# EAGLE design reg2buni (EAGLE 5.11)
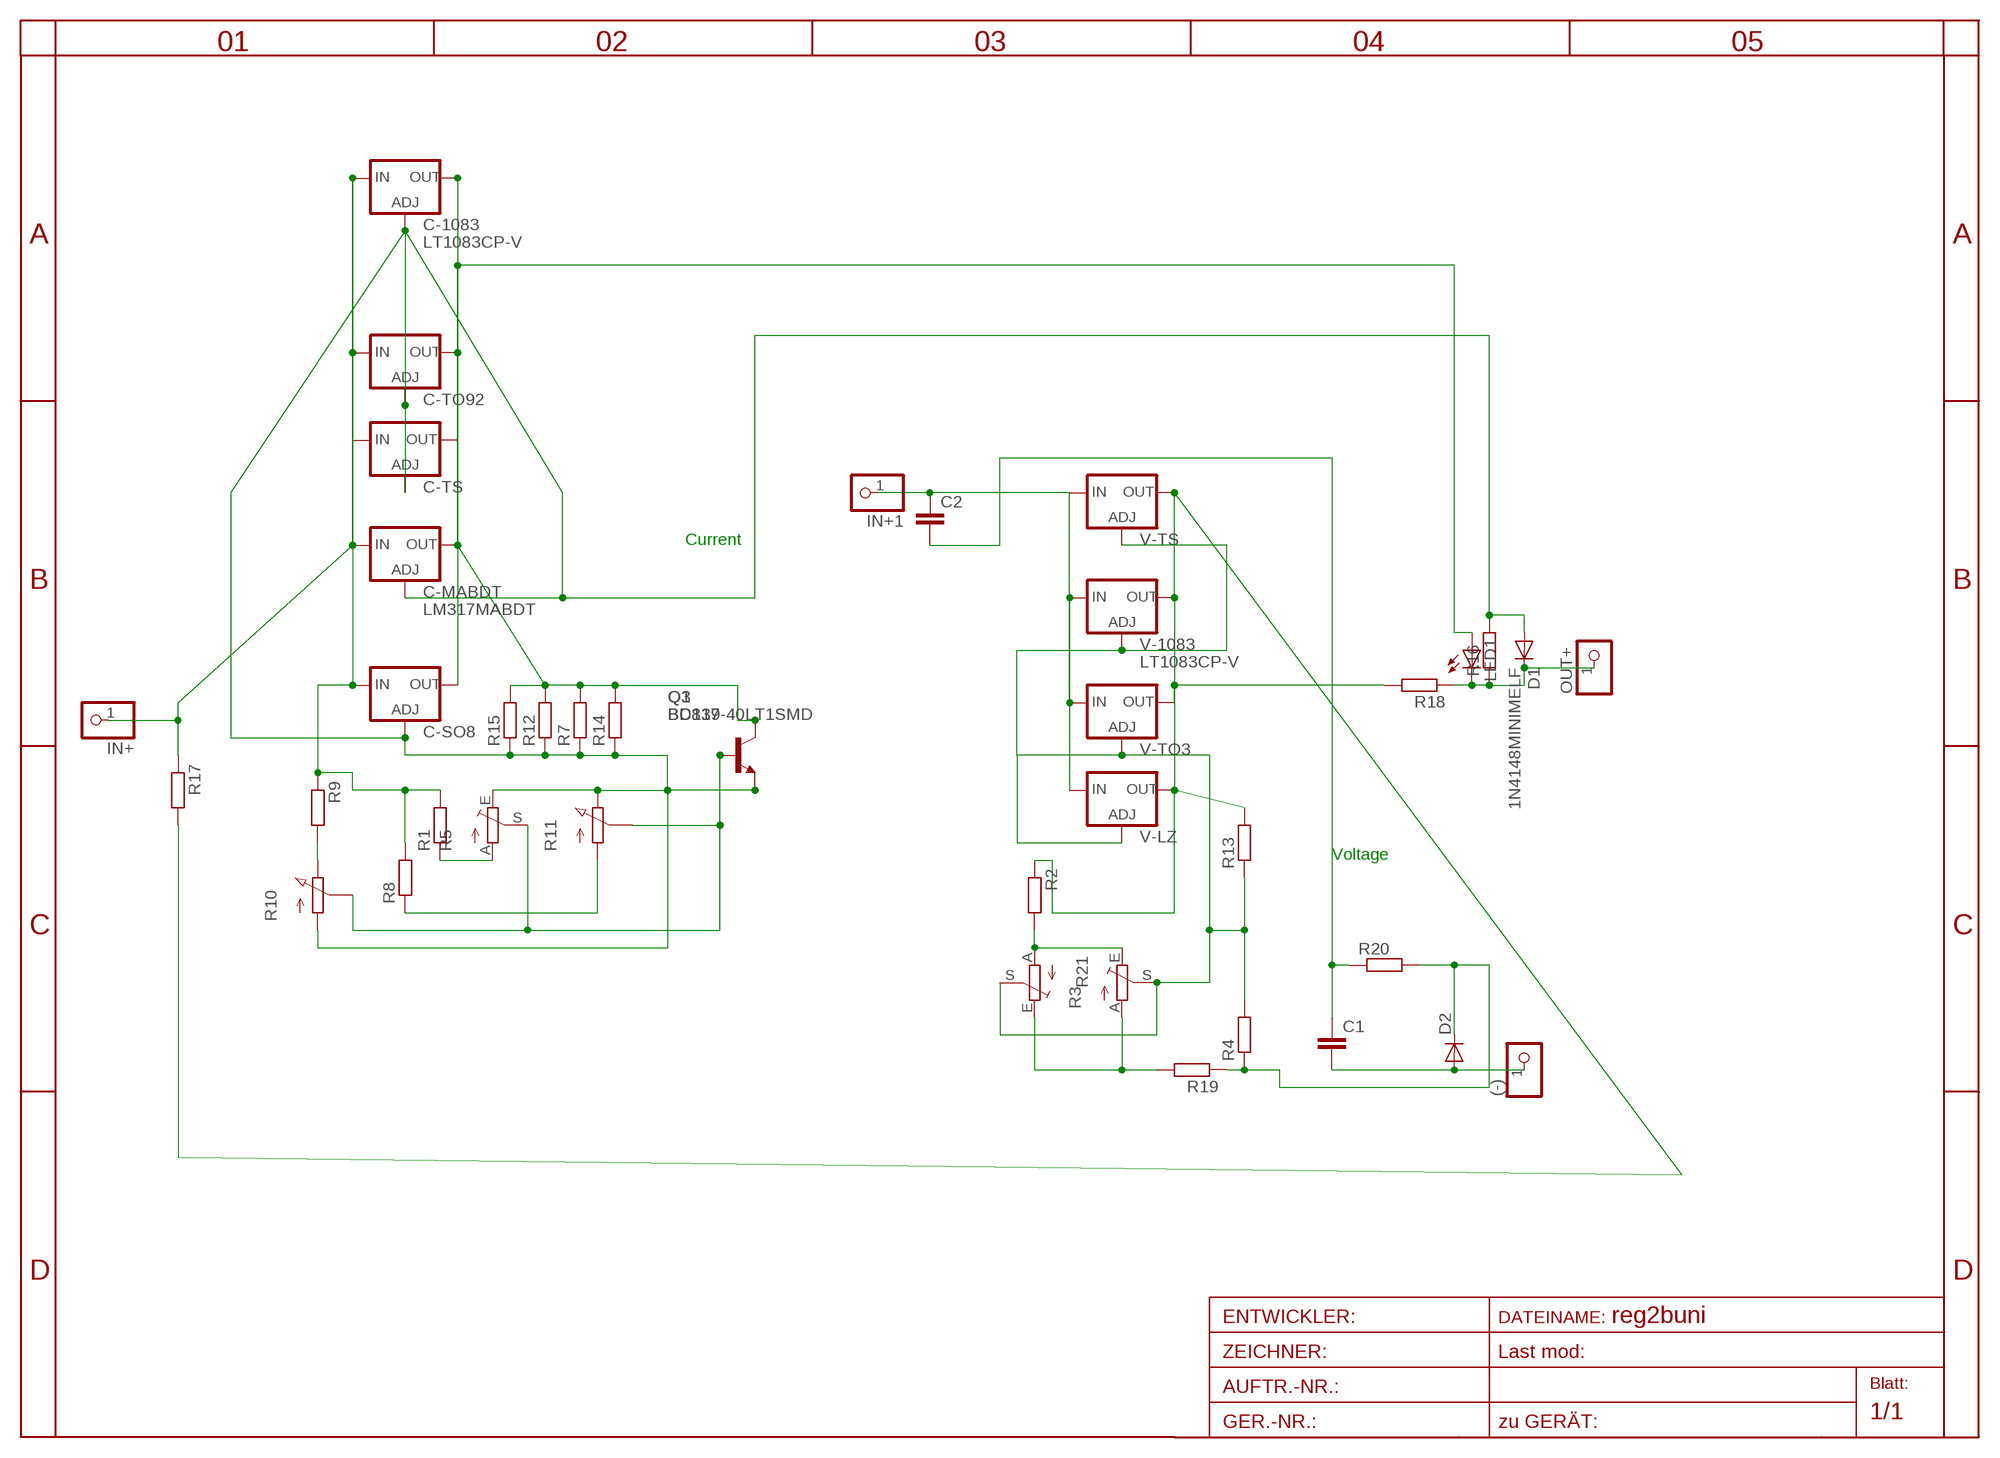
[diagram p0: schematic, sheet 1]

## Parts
(-)  PINHD-1X1  [1X01]
C1  C-EU050-025X075  [C050-025X075]
C2  C-EU050-025X075  [C050-025X075]
C-1083  LT1083CP-V  [TO247S]
C-MABDT  LM317MABDT  [DPACK]
C-SO8  LM317LM-OUTPIN7  [SO08]
C-TO92  LM317LZ  [317L]
C-TS  LM317TS  [317TS]
D1  1N4148MINIMELF  [MINIMELF]
D2  DIODE-MINIMELF  [MINIMELF]
IN+  PINHD-1X1  [1X01]
IN+1  PINHD-1X1  [1X01]
LED1  LEDCHIPLED_1206  [CHIPLED_1206]
OUT+  PINHD-1X1  [1X01]
Q1  BC817-40LT1SMD  [SOT23-BEC]
Q3  BD139  [TO126V]
R1  R-EU_0207/15  [0207/15]
R2  R-EU_0207/10  [0207/10]
R3  TRIM_EU-LI15  [LI15]
R4  R-EU_0204/7  [0204/7]
R5  TRIM_EU-LI15  [LI15]
R7  R-EU_R1206  [R1206]
R8  R-EU_R1206  [R1206]
R9  R-EU_R1206  [R1206]
R10  PC25  [PC25]
R11  PC25  [PC25]
R12  R-EU_R1206  [R1206]
R13  R-EU_0204/5  [0204/5]
R14  R-EU_R1206  [R1206]
R15  R-EU_R1206  [R1206]
R16  R-EU_R0402  [R0402]
R17  R-EU_R0402  [R0402]
R18  R-EU_R0402  [R0402]
R19  R-EU_R0402  [R0402]
R20  R-EU_0207/12  [0207/12]
R21  TRIM_EU-EVND_H  [EVND8AA]
V-1083  LT1083CP-V  [TO247S]
V-LZ  LM317LZ  [317L]
V-TO3  LM317-TO3  [TO3-K02]
V-TS  LM317TS  [317TS]

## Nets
ADJ2: R3.S R4.2 R13.1 R21.S V-1083.1(ADJ) V-LZ.1(ADJ) V-TO3.2(ADJ) V-TS.1(ADJ)
ADJUST: C-1083.1(ADJ) C-MABDT.1(ADJ) C-SO8.4(ADJ) C-TO92.1(ADJ) C-TS.1(ADJ) D1.A Q1.E Q3.3(E) R5.E R7.1 R10.A R11.E R12.1 R14.1 R15.1 R16.2
B1: Q1.B Q3.1(B) R5.S R10.S R11.S
IN+1: C2.1 IN+1.1 V-1083.3(IN) V-LZ.3(IN) V-TO3.1(IN) V-TS.3(IN)
IN-: (-).1 C1.2 D2.A
INPUT+: C-1083.3(IN) C-MABDT.3(IN) C-SO8.1(IN) C-TO92.3(IN) C-TS.3(IN) IN+.1 R1.2 R8.2 R9.1 R17.1
MINUS: R1.1 R5.A
N$1: R3.A R19.2 R21.E
N$2: R2.2 R3.E R21.A
N$5: R8.1 R11.A
N$6: R9.2 R10.E
N$7: C1.1 C2.2 R20.1
OUT1: C-1083.2(OUT) C-MABDT.4(OUT) C-SO8.7(OUT) C-TO92.2(OUT) C-TS.2(OUT) LED1.A Q1.C Q3.2(C) R7.2 R12.2 R14.2 R15.2
OUT2: R2.1 R13.2 R17.2 R18.2 V-1083.2(OUT) V-LZ.2(OUT) V-TO3.3(OUT) V-TS.2(OUT)
OUT+: D1.C LED1.C OUT+.1 R16.1 R18.1
VIRT-: D2.C R4.1 R19.1 R20.2

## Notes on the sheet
- Current
- Voltage

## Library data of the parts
(-) IN+ IN+1 OUT+ = pinhead(2):PINHD-1X1: PIN HEADER
C1 C2 = rcl:C-EU: CAPACITOR, European symbol
C-1083 V-1083 = linear-technology-2:LT1083*: 7.5A Low Dropout Positive Adjustable Regulators
C-MABDT = v-reg:LM317?*: 500 mA Adjustable Output Positive Voltage Regulator Source: http://www.onsemi.co.jp .. LM317M-D.PDF
C-SO8 C-TO92 V-LZ = v-reg-3:LM317L: Adjustable Voltage Regulator, 1.2V to 37V, 100mA
C-TS V-TS = v-reg:LM317TS: VOLTAGE REGULATOR
D1 = diode-1:1N4148: DIODE
D2 = diode:DIODE-: DIODE
LED1 = led:LED: LED
Q1 = transistor-npn:BC817*: NPN Transistor
Q3 = transistor-npn:BD139*: NPN Transistor
R1 R2 R4 R7-R9 R12-R20 = rcl-2:R-EU_: RESISTOR, European symbol
R3 R5 R21 = pot:TRIM_EU-: POTENTIOMETER
R10 R11 = pot-vitrohm:PC25: VITROHM POTENTIOMETER
V-TO3 = v-reg:LM317-TO3: VOLTAGE REGULATOR

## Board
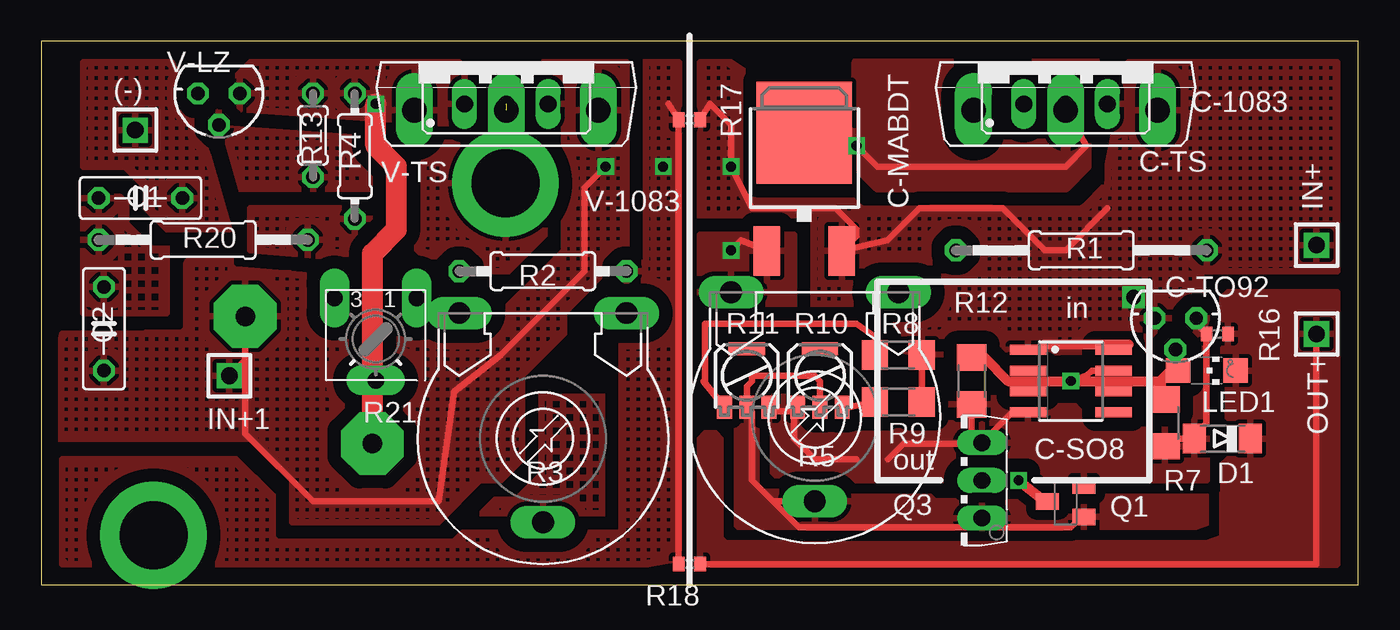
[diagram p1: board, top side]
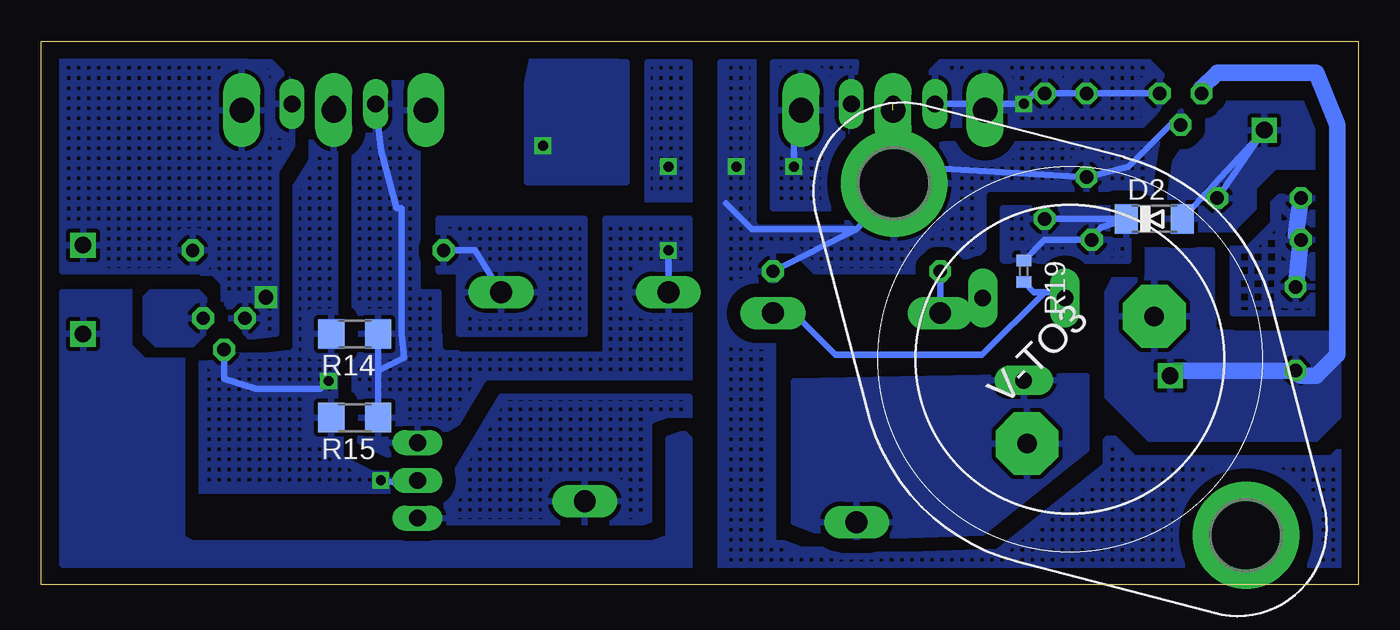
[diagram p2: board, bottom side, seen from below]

Size 80.01 x 33.02 mm. Coordinates in mm from the lower left corner, seen from the top.
Outline: 0,0 80.01,0 80.01,33.02 0,33.02 0,0
Copper layers (1*16): Top 0.035mm / dielectric 1.5mm / Bottom 0.035mm
Design rules "default": minimum track width 10mil, minimum drill 24mil, track to track 8mil, track to pad 8mil, pad to pad 8mil, via to via 8mil, smd to smd 8mil, copper to edge 40mil, drill to drill 8mil, minimum pad ring 10mil, minimum via ring 8mil, stop-mask expansion 4mil, vias tented up to drill 0mil, thermal gap 10mil

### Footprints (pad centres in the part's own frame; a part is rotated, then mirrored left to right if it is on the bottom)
1X01 = drill 1.016 square: 1 0,0
C050-025X075 = drill 0.813 octagon: 1 -2.54,0; 2 2.54,0
TO247S = drill 1.499 long: 1 -5.588,-2.921; 2 0,-2.921; 3 5.588,-2.921
DPACK = smd 1.6 x 3: 1 -2.28,-4.8; 3 2.28,-4.8 | smd 5.8 x 6.2: 4 0,2.38
SO08 = smd 0.6 x 2.2: 1 -1.905,-2.6; 2 -0.635,-2.6; 3 0.635,-2.6; 4 1.905,-2.6; 5 1.905,2.6; 6 0.635,2.6; 7 -0.635,2.6; 8 -1.905,2.6
317L = drill 0.813 octagon: 1 -1.27,0; 2 0,1.905; 3 1.27,0
317TS = drill 1.016 long: 1 -2.54,-2.54; 2 0,-2.54; 3 2.54,-2.54
MINIMELF = smd 1.4 x 1.8: A 1.7,0; C -1.7,0
CHIPLED_1206 = smd 1.5 x 1.5: A 0,-1.75; C 0,1.75
SOT23-BEC = smd 1 x 1.4: B -0.95,-1.1; C 0,1.1; E 0.95,-1.1
TO126V = drill 1.016 long: 1 -2.286,-1.27; 2 0,-1.27; 3 2.286,-1.27
0207/15 = drill 0.813 octagon: 1 -7.62,0; 2 7.62,0
0207/10 = drill 0.813 octagon: 1 -5.08,0; 2 5.08,0
LI15 = drill 1.321 long: A -5.08,-7.62; E 5.08,-7.62; S 0,5.08
0204/7 = drill 0.813 octagon: 1 -3.81,0; 2 3.81,0
R1206 = smd 1.6 x 1.803: 1 -1.422,0; 2 1.422,0
PC25 = smd 2.2 x 0.8: 4 0,1.65 | smd 0.9 x 1.4: A -1.35,-1.9; E 1.35,-1.9; S 0,-1.9
0204/5 = drill 0.813 octagon: 1 -2.54,0; 2 2.54,0
R0402 = smd 0.7 x 0.9: 1 -0.65,0; 2 0.65,0
0207/12 = drill 0.813 octagon: 1 -6.35,0; 2 6.35,0
EVND8AA = drill 1 pad 1.778 long: A -2.5,-2.5; E 2.5,-2.5; S 0,2.5
TO3-K02 = drill 1.194 pad 3.81 octagon: 1 -1.778,-5.461; 2 -1.778,5.461 | drill 4.115 pad 6.477 round: 3 15.113,0; 3@ -15.113,0

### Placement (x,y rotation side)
(-)  5.71,27.62 0 top
C1  6.03,23.5 0 top
C2  3.81,15.56 90 top
C-1083  62.23,31.75 0 top
C-MABDT  46.35,25.08 0 top
C-SO8  62.55,12.38 270 top
C-TO92  68.9,16.19 180 top
C-TS  62.23,31.75 0 top
D1  71.75,8.89 180 top
D2  12.38,22.23 0 bottom
IN+  77.47,20.64 0 top
IN+1  11.43,12.7 0 top
LED1  70.8,13.02 270 top
OUT+  77.47,15.24 0 top
Q1  62.23,5.08 90 top
Q3  55.88,6.35 90 top
R1  63.18,20.32 0 top
R2  30.48,19.05 180 top
R3  30.48,8.89 180 top
R4  19.05,26.04 90 top
R5  46.99,10.16 180 top
R7  68.26,9.84 90 top
R8  52.07,13.97 0 top
R9  52.07,11.11 180 top
R10  47.31,12.7 0 top
R11  42.86,12.7 0 top
R12  56.52,12.38 90 top
R13  16.51,27.3 270 top
R14  60.96,15.24 180 bottom
R15  60.96,10.16 180 bottom
R16  71.44,15.24 180 top
R17  39.37,28.26 180 top
R18  39.37,1.27 180 top
R19  20.32,19.05 270 bottom
R20  9.84,20.95 0 top
R21  20.32,14.92 180 top
V-1083  28.26,31.75 0 top
V-LZ  10.79,29.84 180 top
V-TO3  17.52,13.71 135 bottom
V-TS  28.26,31.75 0 top

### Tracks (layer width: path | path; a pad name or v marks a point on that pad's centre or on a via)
ADJ2  (via drill 0.6)
  Top 1.27: V-TO3.2 20.12,20.12 21.59,21.59 21.59,25.4 20.32,26.67 v20.32,29.21
  Bottom 0.406: V-LZ.1 R13.1 R4.2 19.68,29.84 v20.32,29.21 21.59,29.21 22.32,28.48 | 22.32,28.48 V-1083.1 23.05,29.21 V-TS.1 | 22.32,28.48 21.78,27.94
  pour Bottom (isolate 0.813, hatched): 11.43,30.48 12.7,31.75 25.4,31.75 26.67,30.48 26.67,29.21 25.4,27.94 12.7,27.94
  pour Bottom (isolate 0.813, rank 2): 16.51,12.7 34.29,12.38 34.29,3.81 31.75,2.86 22.86,3.17 16.51,8.26
  pour Top (isolate 0.813, rank 5, hatched): 29.21,11.43 34.29,11.43 34.29,3.81 25.4,3.81
  pour Top (isolate 0.813, hatched): 11.43,30.48 12.7,31.75 25.4,31.75 26.67,30.48 26.67,29.21 25.4,27.94 12.06,28.89
ADJUST  (via drill 0.6)
  Top 0.406: C-SO8.4 58.99,10.48 Q3.3 | 49.53,7.62 46.99,7.62 45.72,8.89 45.72,10.56 | 45.72,10.56 R10.A | 45.72,10.56 44.45,10.56 R11.E | 51.44,7.62 52.39,8.57 57.09,8.57 Q3.3 | R12.1 56.52,9.27 Q3.3 | C-MABDT.1 42.51,20.92 v41.91,20.32 | C-TO92.1 70.17,15.86 R16.2 70.79,9.83 69.85,8.89 68.43,8.89 R7.1
  Bottom 0.406: 59.69,10.01 R15.1 59.54,13.02 | C-TS.1 59.37,26.35 58.42,22.86 58.1,22.86 58.1,15.24 57.95,13.8 59.54,13.02 | 59.54,13.02 R14.1 | 57.4,8.89 57.15,8.89 | R5.E v41.91,20.32
  pour Bottom (isolate 0.813, rank 4, hatched): 45.72,22.23 40.64,22.23 40.64,10.16 52.07,11.43 58.42,7.62 60.96,8.89 60.96,30.48 57.15,30.48 57.15,17.78 55.88,17.78 55.88,15.24 54.61,13.97 45.72,13.97
  pour Top (isolate 0.813): 40.01,21.27 45.72,21.27 45.72,16.51 40.32,16.51 40.01,16.83
  pour Top (isolate 0.813): 44.45,11.43 44.45,6.35 70.8,6.35 70.8,16.83 67.31,11.43 66.04,10.16 63.5,10.16 62.23,11.43
  pour Bottom (isolate 0.61): 69.85,16.51 69.85,17.14 70.48,17.78 73.34,17.78 73.66,17.46 73.66,15.24 73.03,14.61 70.8,14.61 70.17,15.24
B1
  Top 0.406: R10.S 47.31,12.38 46.99,12.7 43.18,12.7 43.18,12.38 42.86,12.06 R11.S 43.18,10.48 43.18,6.35 44.45,5.08 | 44.45,5.08 R5.S | Q1.B 63.19,4.13 62.55,3.49 46.04,3.49 44.45,5.08
  pour Bottom (isolate 0.813, rank 3, hatched): 40.64,11.43 52.07,11.43 55.88,5.08 58.42,3.81 40.64,3.81
  pour Top (isolate 0.61, rank 3): 41.91,10.16 41.91,2.54 69.85,2.54 71.12,3.81 71.12,5.08 70.48,5.71 65.09,5.71 64.45,5.08 54.29,5.08 53.66,5.71 45.4,5.71 44.13,6.99 44.13,10.48
IN+1  (via drill 0.6)
  Top 0.406: v34.29,25.4 33.02,24.13 33.02,19.05 27.94,13.97 25.08,11.75 24.13,5.08 16.51,5.08 12.4,9.19 V-TO3.1 12.4,13.67 IN+1.1
  Bottom 0.406: 11.11,13.02 IN+1.1 | 3.49,12.7 C2.1 | v34.29,25.4 34.29,28.38 V-1083.3
  Bottom 1.016: C2.1 11.11,13.02 | V-LZ.3 9.53,30.16 8.57,31.11 2.54,31.11 1.27,27.94 1.27,13.97 2.54,12.7 3.49,12.7
  pour Bottom (isolate 0.813, hatched): 30.48,31.75 35.56,31.75 35.56,22.86 31.75,22.86
  pour Top (isolate 0.813, rank 3, hatched): 1.27,15.24 6.35,15.24 8.89,19.68 15.24,19.68 19.05,15.24 26.67,15.24 31.75,20.32 31.75,30.48 30.48,31.75 35.56,31.75 35.56,20.32 31.75,16.51 31.75,15.24 29.21,12.7 29.21,7.62 27.94,6.35 26.67,6.35 24.13,3.81 15.24,3.81 15.24,6.35 12.7,8.89 0,8.89
  pour Bottom (isolate 0.813, rank 3): 15.24,17.78 15.24,11.43 12.7,8.89 2.54,8.89 0,11.43 0,13.97 1.27,15.24 7.62,15.24 8.89,16.51 8.89,20.32 13.97,20.32
IN-
  Bottom 0.406: C1.2 (-).1 D2.A
  pour Bottom (isolate 0.813): 2.54,29.21 8.89,29.21 9.84,27.62 11.11,25.72 11.75,21.59 7.62,21.59 6.35,22.86 6.35,24.13 5.08,25.4 2.54,25.4
  pour Top (isolate 0.813, hatched): 2.54,31.75 7.94,31.75 10.16,26.04 11.43,21.59 7.62,21.59 6.35,22.86 6.35,24.13 5.08,25.4 2.54,25.4
INPUT+  (via drill 0.6, 0.9)
  Top 0.406: R9.1 R8.2 | C-SO8.1 60.64,14.29 60.96,14.61 | 64.77,22.86 62.23,20.32 60.96,20.32 58.42,22.86 53.34,22.86 51.4,20.92 C-MABDT.3 49.53,21.18 49.53,21.59 48.26,22.86 43.18,22.86 v41.91,25.4 41.91,27.94 40.64,29.21 R17.1
  Top 0.61: 60.96,14.61 66.04,14.61
  other vias: 66.36,17.46
  pour Top (isolate 0.813, rank 5, hatched): 66.04,31.75 78.74,31.75 78.74,19.05 70.48,19.05 70.48,14.29 53.34,13.97 46.35,15.88 46.35,21.59 40.01,21.59 40.01,31.75 41.91,31.75 53.34,24.13 64.77,24.13 64.77,25.4
  pour Bottom (isolate 0.813, rank 2, hatched): 66.36,31.75 78.74,32.07 78.74,19.05 70.17,19.05 70.17,17.78 68.58,14.92 65.72,15.24 65.72,25.08 64.77,26.67 64.77,30.48 66.04,31.75
  pour Bottom (isolate 0.813, rank 5, hatched): 40.64,31.75 40.64,22.86 43.18,22.86 43.18,31.75
MINUS
  Bottom 0.406: R5.A 53.66,20.32 R1.1
  pour Bottom (isolate 0.813, rank 3, hatched): 46.99,22.23 55.88,22.23 55.88,19.05 54.61,19.05 54.61,15.24 46.99,15.24
N$1
  Bottom 0.406: R3.A 34.29,16.51 31.75,13.97 22.86,13.97 19.05,17.78 | 19.05,17.78 19.7,17.78 R19.2 | R21.E 17.82,17.74 17.78,17.78 19.05,17.78
N$2
  Bottom 0.406: R2.2 R3.E 23.73,16.51 R21.A
N$5
  Top 0.406: R8.1 50.65,15.07 49.53,15.88 40.32,15.88 40.32,12.38 40.24,12.38 R11.A
N$6
  Top 0.406: R10.E 49.07,10.8 R9.2
N$7
  Bottom 0.406: R20.1 3.81,21.27
  Bottom 1.016: C2.2 R20.1 | 3.81,21.27 C1.1
  pour Bottom (isolate 0.813, rank 2, hatched): 2.54,24.13 2.54,16.51 7.62,16.51 7.62,22.86
  pour Top (isolate 0.813, rank 2, hatched): 2.54,24.13 2.54,16.51 7.62,16.51 7.62,22.86
OUT1  (via drill 0.6)
  Top 0.406: C-MABDT.4 48.1,28.1 50.8,25.4 62.23,25.4 63.5,26.67 C-1083.2 | 60.96,5.08 Q1.C | v62.55,12.38 63.5,12.7 63.82,13.02 C-SO8.7 | R7.2 68.11,12.38 67.94,12.38 | R12.2 57.32,13.8 | 68.58,13.02 LED1.A
  Top 0.61: v59.37,6.35 60.96,5.08 | 57.32,13.8 58.74,12.38 v62.55,12.38 67.94,12.38 68.58,13.02
  Bottom 0.406: v59.37,6.35 57.47,6.03 Q3.2 | C-TO92.2 68.9,12.53 66.99,11.9 63.03,11.9 v62.55,12.38
  other vias: 49.53,26.67
  pour Bottom (isolate 0.813, rank 5, hatched): 62.55,28.89 64.45,29.53 65.41,22.23 65.41,14.29 69.22,14.29 70.48,13.65 70.8,5.71 57.47,5.71
  pour Top (isolate 0.813, rank 3): 49.53,31.75 64.77,31.75 63.5,29.21 63.5,25.4 62.23,24.13 50.8,24.13 49.53,25.4
  pour Bottom (isolate 0.813, rank 4): 44.45,31.75 44.45,24.45 50.48,24.45 50.48,30.48 50.16,32.07
OUT2  (via drill 0.6)  (1 unrouted)
  Top 0.406: 38.1,29.21 R17.2 R18.2
  Bottom 0.406: 38.42,23.18 36.83,21.59 30.48,21.59 | 30.48,21.59 R2.1 | V-TO3.3 27.2,25.4 R13.2 13.97,25.4 11.43,27.94 V-LZ.2 | V-TO3.3 28.2,28.77 V-1083.2 | V-TO3.3 28.2,23.87 30.48,21.59 | v37.78,25.4 38.1,25.4
  pour Bottom (isolate 0.813, rank 4, hatched): 10.16,29.21 12.7,29.21 13.97,27.94 29.21,27.94 31.75,25.4 31.75,24.13 33.02,22.86 35.56,22.86 35.56,31.75 38.73,31.75 38.73,0.32 1.27,0 0,0 0,8.89 15.24,8.89 21.59,2.54 35.56,2.54 35.56,20.32 34.29,20.32 33.02,19.05 24.13,19.05 20.32,22.86 11.43,22.86 10.16,24.13
  pour Top (isolate 0.813, rank 4, hatched): 10.16,29.21 12.7,29.21 13.97,27.94 29.21,27.94 31.75,25.4 31.75,24.13 33.02,22.86 35.56,22.86 35.56,31.75 38.73,31.75 38.73,1.59 36.83,1.27 1.27,1.27 1.27,7.62 13.97,7.62 14.61,3.17 35.24,3.17 35.24,20.32 34.29,20.32 33.02,19.05 24.13,19.05 20.32,22.86 11.43,22.86 10.16,24.13
OUT+
  Top 0.406: OUT+.1 77.47,1.27 R18.1
  pour Top (isolate 0.61, rank 2): 72.07,17.78 78.74,17.78 78.74,1.27 78.11,0.64 40.64,0.64 40.01,1.27 40.01,8.89 40.32,9.21 40.96,9.21 41.27,8.89 41.27,2.86 41.59,2.54 70.8,2.54 71.75,2.86 71.75,7.3 72.07,7.62 73.03,7.62 73.03,10.16 72.07,10.16 72.07,13.34 71.75,13.65 71.75,17.46
  pour Bottom (isolate 0.61, rank 2): 71.44,17.78 78.74,17.78 78.74,1.27 78.11,0.64 40.64,0.64 40.64,8.89 40.96,9.21 41.91,8.89 41.91,2.86 42.86,2.54 70.8,2.54 71.44,2.86
VIRT-
  Bottom 0.406: R19.1 19.07,20.95 R20.2 15.67,21.7 D2.C R4.1
  pour Bottom (isolate 0.813, hatched): 13.97,22.86 21.59,22.86 21.59,19.68 13.97,19.68
  pour Top (isolate 0.813, hatched): 12.7,22.86 20.32,22.86 20.32,19.68 12.7,20.32

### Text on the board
tNames: in | out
